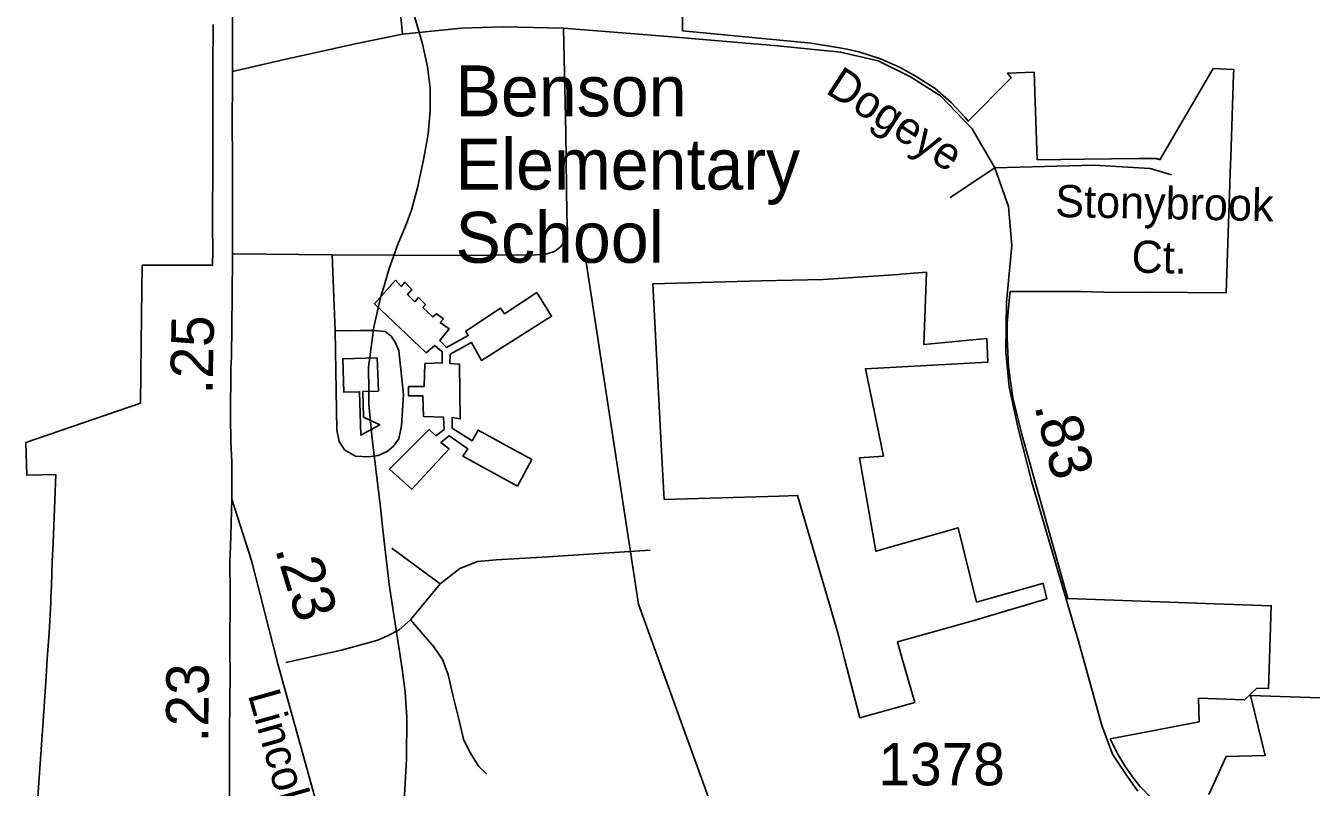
# Model space of a CAD drawing. Extents: x 2082433 to 2279600, y 546599 to 755198.
# Drawn here: x 2131295 to 2135079, y 599621 to 601864 of the extents above; entities that cross this region are included whole.
import ezdxf

# ---------------------------------------------------------------- set-up
doc = ezdxf.new("R2010")
doc.units = 0
for name, color, linetype in [('Exist Boundary Political City Limit New', 7, 'Continuous'), ('Exist Cultural Educational Facility Elementary CELL', 7, 'Continuous'), ('Exist Cultural Educational Facility Elementary Footprint', 7, 'Continuous'), ('Exist Cultural Educational Facility Elementary Label', 7, 'Continuous'), ('Exist Hydrographic Misc Water Feature', 7, 'Continuous'), ('Exist Road Non-System Type 51', 7, 'Continuous'), ('Exist Road Non-System Type 51 Label', 7, 'Continuous'), ('Exist Road Primary NC Attributed', 7, 'Continuous'), ('Exist Road Primary NC Service Mileage Hundredths English Label', 7, 'Continuous'), ('Exist Road Secondary Mileage Hundredths English Label', 7, 'Continuous'), ('Exist Road Secondary Type 51 Attributed', 7, 'Continuous'), ('Exist Road Secondary Type 51 Label', 7, 'Continuous'), ('Exist Road Secondary Type 51 Number Label', 7, 'Continuous'), ('Map Preparation Boundary City Limit Buffer Line', 7, 'Continuous')]:
    doc.layers.add(name, color=color, linetype=linetype)

msp = doc.modelspace()

# ---------------------------------------------------------------- linework, layer by layer
at = {"layer": 'Exist Boundary Political City Limit New'}
for points in [[(2133713, 601795), (2133684.8, 601799.8), (2133606.8, 601812.8), (2133382.2, 601834.2), (2133229, 601848.9), (2133227, 602109.6)], [(2131847, 601867.1), (2131846.5, 601738.4), (2131846.2, 601641.3), (2131846.2, 601635.6), (2131846.2, 601609.8), (2131845.8, 601480.3), (2131845.2, 601271.4), (2131845.8, 601201.5), (2131845.5, 601158.4), (2131638.2, 601158.4), (2131636.5, 601011.7), (2131633.2, 600752.4), (2131295.2, 600636.8), (2131298.2, 600540.1), (2131383.8, 600542.1), (2131375.8, 600341.2), (2131373.5, 600286.1), (2131370.8, 600215.6), (2131369.2, 600179.6), (2131368.8, 600165.2), (2131364, 600076.1), (2131358.8, 600000), (2131355.2, 599946.8), (2131346.2, 599816.2), (2131341.8, 599747.6), (2131338.8, 599704.1), (2131338, 599691.8), (2131328.2, 599550.5)], [(2134608.5, 599589.9), (2134577.5, 599621.6), (2134577, 599622.1), (2134553.5, 599651.8), (2134530.5, 599684.4), (2134507.2, 599723.7), (2134492, 599753.8), (2134487.8, 599763.6), (2134601.2, 599785.4), (2134749.2, 599813.9), (2134747.8, 599883.8), (2134882.8, 599879.2), (2134919.2, 599913.4), (2134953, 599912.2), (2134956, 600000), (2134961.5, 600156.1), (2134795.2, 600161.9), (2134362.5, 600177.1), (2134227.8, 600659.9), (2134201, 600768.5), (2134188.2, 600860.6), (2134184, 600944.2), (2134184, 600987.6), (2134191.5, 601064.6), (2134193.2, 601081.6), (2134402.2, 601081.4), (2134502.5, 601078.6), (2134601.5, 601079.2), (2134829.2, 601077.8), (2134842, 601457.6), (2134842.5, 601476.8), (2134850.8, 601720.5), (2134851.2, 601735.2), (2134790.5, 601738.1), (2134634, 601469.4), (2134632.2, 601470.2), (2134630.5, 601470.8), (2134628.5, 601471.4), (2134626.5, 601471.9), (2134624.8, 601472.4), (2134622.8, 601472.7), (2134620.8, 601472.9), (2134618.8, 601473.2), (2134616.8, 601473.2), (2134615, 601473.3), (2134613, 601473.2), (2134611, 601473.1), (2134609, 601472.9), (2134570.5, 601472.5), (2134411.8, 601470.9), (2134273, 601469.4), (2134263.5, 601727), (2134185, 601724.2), (2134196, 601710.2), (2134069.5, 601582.4), (2134061, 601593.2), (2134019, 601638.1), (2133972.5, 601678.9), (2133916, 601714.1), (2133867.2, 601742.3), (2133811, 601766.8), (2133748, 601786.8), (2133713, 601795)], [(2133912, 599871.3), (2133875.2, 600000), (2133861.2, 600049.2), (2133956.5, 600076.1), (2134082.8, 600111.8), (2134300.5, 600176.6), (2134290, 600221.7), (2134288, 600221.1), (2134094.2, 600166.8), (2134039.8, 600385.4), (2133797.5, 600316.6), (2133750, 600591.2), (2133820.2, 600596.6), (2133766.8, 600853.7), (2134127.5, 600873.2), (2134124, 600942.6), (2133938.5, 600925.6), (2133946.8, 601137.8), (2133872, 601132), (2133864, 601131.5), (2133642.8, 601116.9), (2133459.8, 601112.4), (2133141.5, 601104.2), (2133168.2, 600592.1), (2133174.8, 600468.8), (2133513.2, 600478.6), (2133567.2, 600480.1), (2133686, 600076.1), (2133705.8, 600000), (2133751, 599825.9), (2133912, 599871.3)], [(2135127.5, 599884.4), (2135076.5, 599886), (2134900, 599892.1), (2134943.2, 599714.6), (2134828.5, 599712.3), (2134777.8, 599600)]]:
    msp.add_lwpolyline(points, dxfattribs=at)
at = {"layer": 'Exist Cultural Educational Facility Elementary CELL'}
msp.add_lwpolyline([(2132330.2, 600886), (2132333.4, 600788.1), (2132287.4, 600786.6), (2132289.8, 600711.5), (2132337.6, 600688.8), (2132282, 600657.8), (2132277.8, 600786.3), (2132231.8, 600784.8), (2132228.6, 600882.6)], close=True, dxfattribs=at)
at = {"layer": 'Exist Cultural Educational Facility Elementary Footprint'}
msp.add_lwpolyline([(2132383.9, 601114.7), (2132321.7, 601045.1), (2132473.6, 600900.3), (2132499.2, 600922.3), (2132521.2, 600904), (2132521.2, 600871), (2132469.9, 600869.2), (2132468.1, 600801.4), (2132422.3, 600801.4), (2132422.3, 600773.9), (2132464.4, 600773.9), (2132466.3, 600713.5), (2132524.8, 600711.6), (2132526.7, 600675), (2132502.9, 600656.7), (2132482.7, 600675), (2132365.6, 600557.7), (2132431.5, 600499.1), (2132541.3, 600618.2), (2132517.5, 600636.5), (2132541.3, 600656.7), (2132596.2, 600618.2), (2132581.6, 600596.2), (2132742.7, 600508.3), (2132784.8, 600587), (2132627.4, 600673.2), (2132609.1, 600642), (2132550.5, 600678.7), (2132550.5, 600709.8), (2132574.3, 600706.1), (2132572.4, 600867.4), (2132543.2, 600869.2), (2132545, 600896.7), (2132607.2, 600931.5), (2132636.5, 600878.3), (2132843.4, 601008.4), (2132799.4, 601078), (2132704.2, 601015.8), (2132693.3, 601032.2), (2132590.7, 600964.5), (2132598.1, 600951.6), (2132534, 600916.8), (2132513.9, 600937), (2132541.3, 600971.8), (2132515.7, 600990.1), (2132524.8, 601001.1), (2132504.7, 601015.8), (2132493.7, 601006.6), (2132464.4, 601034.1), (2132471.8, 601043.2), (2132451.6, 601063.4), (2132440.6, 601050.6), (2132418.7, 601072.6), (2132431.5, 601087.2), (2132411.4, 601109.2), (2132400.4, 601096.4)], close=True, dxfattribs=at)
at = {"layer": 'Exist Hydrographic Misc Water Feature'}
msp.add_line((2132485.5, 601618.5), (2132485.5, 601614.7), dxfattribs=at)
for points in [[(2132299.9, 602360.6), (2132325.3, 602230.2), (2132427.2, 601933.8), (2132449.8, 601857.4)], [(2132299.9, 602360.6), (2132325.3, 602230.2), (2132427.2, 601933.8), (2132449.8, 601857.4)], [(2132449.8, 601857.4), (2132463.7, 601810.2), (2132477.5, 601743.3), (2132485.7, 601679.6), (2132485.5, 601618.5)], [(2132449.8, 601857.4), (2132463.7, 601810.2), (2132477.5, 601743.3), (2132485.7, 601679.6), (2132485.5, 601618.5)], [(2132485.5, 601614.7), (2132479.7, 601544.2), (2132465.4, 601464.1), (2132452.5, 601405.1)], [(2132485.5, 601614.7), (2132479.7, 601544.2), (2132465.4, 601464.1), (2132452.5, 601405.1)], [(2132452.5, 601405.1), (2132448.4, 601386.7), (2132430.5, 601320.5), (2132413.3, 601274), (2132391.4, 601222.4), (2132365.3, 601149.1), (2132349.9, 601097.8)], [(2132452.5, 601405.1), (2132448.4, 601386.7), (2132430.5, 601320.5), (2132413.3, 601274), (2132391.4, 601222.4), (2132365.3, 601149.1), (2132349.9, 601097.8)], [(2133237.5, 599062.4), (2133320.5, 599136.2), (2133353.5, 599270), (2133343.5, 599535.9), (2133318.7, 599552.8), (2133099.5, 600160.9), (2132944.7, 601167.9)], [(2132349.9, 601097.8), (2132339.7, 601063.7), (2132319.6, 600975.9), (2132304.4, 600858.2), (2132305, 600789.2)], [(2132349.9, 601097.8), (2132339.7, 601063.7), (2132319.6, 600975.9), (2132304.4, 600858.2), (2132305, 600789.2)], [(2132305, 600789.2), (2132305.4, 600748.2), (2132316.5, 600638.2), (2132339.5, 600444.9), (2132346.7, 600379.9)], [(2132305, 600789.2), (2132305.4, 600748.2), (2132316.5, 600638.2), (2132339.5, 600444.9), (2132346.7, 600379.9)], [(2132346.7, 600379.9), (2132364.7, 600218.9), (2132403.5, 599970), (2132412.5, 599901.4)], [(2132346.7, 600379.9), (2132364.7, 600218.9), (2132403.5, 599970), (2132412.5, 599901.4)], [(2132412.5, 599901.4), (2132417.2, 599828), (2132416.2, 599704.1), (2132408.6, 599562)], [(2132412.5, 599901.4), (2132417.2, 599828), (2132416.2, 599704.1), (2132408.6, 599562)]]:
    msp.add_lwpolyline(points, dxfattribs=at)
at = {"layer": 'Exist Road Non-System Type 51'}
for p, q in [((2134147.7, 601445.1), (2134016.5, 601358.3)), ((2132196.9, 601188.8), (2131903.9, 601192.5)), ((2132196.9, 601188.8), (2132206.3, 600965)), ((2132515, 600220.6), (2132372.7, 600325.2)), ((2132427.6, 600114.3), (2132515, 600220.6))]:
    msp.add_line(p, q, dxfattribs=at)
for points in [[(2132404.4, 601838.8), (2132394.1, 601941.7), (2132397.5, 602295)], [(2132878.6, 601856.8), (2132885.5, 601548.1), (2132888.1, 601307.1), (2132889.8, 601260.8), (2132886.3, 601233.4), (2132869.2, 601212.8), (2132852, 601199.1), (2132822.9, 601190.5), (2132797.2, 601188.8), (2132565.6, 601187.1), (2132196.9, 601188.8)], [(2134147.7, 601445.1), (2134440.2, 601453.2), (2134605.6, 601443.1), (2134668.2, 601424.9)], [(2132515, 600220.6), (2132573.3, 600265.2), (2132624.8, 600285.8), (2132679.7, 600290.9), (2132832.3, 600299.5), (2133133.3, 600319.2)], [(2132060.5, 599989.1), (2132225.2, 600025.1), (2132331.5, 600054.2), (2132362.4, 600068), (2132395, 600085.1), (2132427.6, 600114.3)], [(2132427.6, 600114.3), (2132496.2, 600035.4), (2132521.9, 599997.6), (2132539, 599953.1), (2132552.8, 599893), (2132571.6, 599817.6), (2132583.6, 599762.7), (2132602.5, 599724.9), (2132629.1, 599682.9), (2132651.4, 599660.6)]]:
    msp.add_lwpolyline(points, dxfattribs=at)
msp.add_lwpolyline([(2132206.3, 600965), (2132211.4, 600673.4), (2132218.3, 600639.1), (2132233.7, 600615.1), (2132266.3, 600596.2), (2132304.1, 600594.5), (2132333.2, 600597.9), (2132358.9, 600609.9), (2132377.8, 600625.4), (2132393.2, 600647.7), (2132401.8, 600685.4), (2132407, 600778), (2132393.2, 600906.7), (2132383, 600932.4), (2132371, 600949.5), (2132353.8, 600963.3), (2132321.2, 600966.7), (2132278.3, 600966.7)], close=True, dxfattribs=at)
at = {"layer": 'Exist Road Primary NC Attributed'}
for points in [[(2131903.6, 601728.8), (2131904.3, 601879), (2131903, 601977.9), (2131902.1, 602090.4), (2131901.2, 602131.4), (2131902.1, 602337), (2131901.6, 602422.7), (2131903, 602554.2), (2131904.8, 602717.8), (2131903, 602761.5), (2131903.6, 602995.1), (2131904.9, 603112.9), (2131904, 603195.1), (2131903.9, 603377.7)], [(2131901.6, 600469.3), (2131901.6, 600579.6), (2131899.4, 600641), (2131898, 600712.4), (2131899.4, 600856.4), (2131901.2, 600888.4), (2131903.4, 601070), (2131903.9, 601183.6), (2131903.5, 601348.8), (2131903.5, 601497), (2131903.4, 601548.8), (2131903.6, 601728.8)], [(2131894, 599263), (2131894.4, 599464.9), (2131894.8, 599593.4), (2131895.3, 599782.7), (2131896.7, 599959.6), (2131895.8, 600017.1), (2131896.7, 600195.1), (2131895.8, 600286.2), (2131898.5, 600329), (2131901.6, 600469.3)]]:
    msp.add_lwpolyline(points, dxfattribs=at)
at = {"layer": 'Exist Road Secondary Type 51 Attributed'}
for points in [[(2131903.6, 601728.8), (2132057.1, 601764.2), (2132269.5, 601811.7), (2132404.4, 601838.8), (2132576.8, 601856.8), (2132700.3, 601860.3), (2132878.6, 601856.8), (2133173.3, 601832.8), (2133508.2, 601804.5), (2133693.8, 601786.3), (2133804.7, 601760.1), (2133899.5, 601713.6), (2133988.3, 601657.1), (2134081.1, 601560.2), (2134147.7, 601445.1), (2134188, 601332), (2134198.1, 601216.9), (2134182, 601049.4), (2134180, 600904), (2134190, 600801), (2134216.3, 600677.8), (2134256.6, 600520.3), (2134393.8, 600051.9), (2134462.4, 599803.6), (2134494.7, 599718.8), (2134537, 599654.2), (2134569.3, 599609.7)], [(2131901.6, 600469.3), (2131959.6, 600289.2), (2132037.2, 599985.3), (2132168.9, 599511), (2132253.6, 599268.4)]]:
    msp.add_lwpolyline(points, dxfattribs=at)
at = {"layer": 'Map Preparation Boundary City Limit Buffer Line'}
for points in [[(2133713, 601795), (2133684.8, 601799.8), (2133606.8, 601812.8), (2133382.2, 601834.2), (2133229, 601848.9), (2133227, 602109.6)], [(2131847, 601867.1), (2131846.5, 601738.4), (2131846.2, 601641.3), (2131846.2, 601635.6), (2131846.2, 601609.8), (2131845.8, 601480.3), (2131845.2, 601271.4), (2131845.8, 601201.5), (2131845.5, 601158.4), (2131638.2, 601158.4), (2131636.5, 601011.7), (2131633.2, 600752.4), (2131295.2, 600636.8), (2131298.2, 600540.1), (2131383.8, 600542.1), (2131375.8, 600341.2), (2131373.5, 600286.1), (2131370.8, 600215.6), (2131369.2, 600179.6), (2131368.8, 600165.2), (2131364, 600076.1), (2131358.8, 600000), (2131355.2, 599946.8), (2131346.2, 599816.2), (2131341.8, 599747.6), (2131338.8, 599704.1), (2131338, 599691.8), (2131328.2, 599550.5)], [(2134608.5, 599589.9), (2134577.5, 599621.6), (2134577, 599622.1), (2134553.5, 599651.8), (2134530.5, 599684.4), (2134507.2, 599723.7), (2134492, 599753.8), (2134487.8, 599763.6), (2134601.2, 599785.4), (2134749.2, 599813.9), (2134747.8, 599883.8), (2134882.8, 599879.2), (2134919.2, 599913.4), (2134953, 599912.2), (2134956, 600000), (2134961.5, 600156.1), (2134795.2, 600161.9), (2134362.5, 600177.1), (2134227.8, 600659.9), (2134201, 600768.5), (2134188.2, 600860.6), (2134184, 600944.2), (2134184, 600987.6), (2134191.5, 601064.6), (2134193.2, 601081.6), (2134402.2, 601081.4), (2134502.5, 601078.6), (2134601.5, 601079.2), (2134829.2, 601077.8), (2134842, 601457.6), (2134842.5, 601476.8), (2134850.8, 601720.5), (2134851.2, 601735.2), (2134790.5, 601738.1), (2134634, 601469.4), (2134632.2, 601470.2), (2134630.5, 601470.8), (2134628.5, 601471.4), (2134626.5, 601471.9), (2134624.8, 601472.4), (2134622.8, 601472.7), (2134620.8, 601472.9), (2134618.8, 601473.2), (2134616.8, 601473.2), (2134615, 601473.3), (2134613, 601473.2), (2134611, 601473.1), (2134609, 601472.9), (2134570.5, 601472.5), (2134411.8, 601470.9), (2134273, 601469.4), (2134263.5, 601727), (2134185, 601724.2), (2134196, 601710.2), (2134069.5, 601582.4), (2134061, 601593.2), (2134019, 601638.1), (2133972.5, 601678.9), (2133916, 601714.1), (2133867.2, 601742.3), (2133811, 601766.8), (2133748, 601786.8), (2133713, 601795)], [(2133912, 599871.3), (2133875.2, 600000), (2133861.2, 600049.2), (2133956.5, 600076.1), (2134082.8, 600111.8), (2134300.5, 600176.6), (2134290, 600221.7), (2134288, 600221.1), (2134094.2, 600166.8), (2134039.8, 600385.4), (2133797.5, 600316.6), (2133750, 600591.2), (2133820.2, 600596.6), (2133766.8, 600853.7), (2134127.5, 600873.2), (2134124, 600942.6), (2133938.5, 600925.6), (2133946.8, 601137.8), (2133872, 601132), (2133864, 601131.5), (2133642.8, 601116.9), (2133459.8, 601112.4), (2133141.5, 601104.2), (2133168.2, 600592.1), (2133174.8, 600468.8), (2133513.2, 600478.6), (2133567.2, 600480.1), (2133686, 600076.1), (2133705.8, 600000), (2133751, 599825.9), (2133912, 599871.3)], [(2135127.5, 599884.4), (2135076.5, 599886), (2134900, 599892.1), (2134943.2, 599714.6), (2134828.5, 599712.3), (2134777.8, 599600)]]:
    msp.add_lwpolyline(points, dxfattribs=at)

# ---------------------------------------------------------------- texts
at = {"layer": 'Exist Cultural Educational Facility Elementary Label'}
for s, p in [('Benson', (2132560.3, 601597.1)), ('Elementary', (2132560.3, 601381.5)), ('School', (2132560.3, 601165.9))]:
    msp.add_text(s, height=150, dxfattribs=at).set_placement(p)
at = {"layer": 'Exist Road Non-System Type 51 Label'}
for s, p in [('Stonybrook', (2134325.1, 601300.7)), ('Ct.', (2134549.7, 601137))]:
    msp.add_text(s, height=95, rotation=358.8759, dxfattribs=at).set_placement(p)
at = {"layer": 'Exist Road Primary NC Service Mileage Hundredths English Label'}
msp.add_text('.23', height=125, rotation=89.5558, dxfattribs=at).set_placement((2131832.6, 599753.2))
at = {"layer": 'Exist Road Secondary Mileage Hundredths English Label'}
for s, rotation, p in [('.25', 88.8485, (2131845.1, 600777.6)), ('.83', 284.3699, (2134263.6, 600744.9)), ('.23', 287.0858, (2132028.2, 600323.1))]:
    msp.add_text(s, height=125, rotation=rotation, dxfattribs=at).set_placement(p)
at = {"layer": 'Exist Road Secondary Type 51 Label'}
for s, rotation, p in [('Dogeye', 327.0905, (2133646.1, 601668.1)), ('Lincoln', 285.7118, (2131948.8, 599894.2))]:
    msp.add_text(s, height=95, rotation=rotation, dxfattribs=at).set_placement(p)
at = {"layer": 'Exist Road Secondary Type 51 Number Label'}
msp.add_text('1378', height=125, dxfattribs=at).set_placement((2133805.5, 599626.9))

doc.saveas('drawing.dxf')
